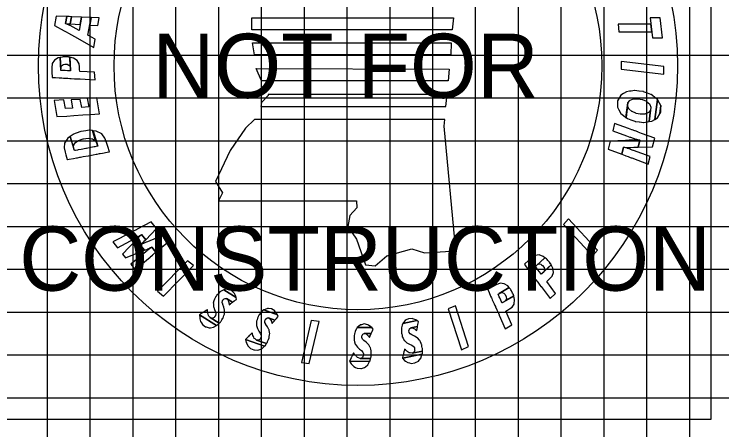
# Model space of a CAD drawing. Extents: x -20 to 684, y -10 to 430.
# Drawn here: x 626.44 to 659.5, y 370.5 to 389.91 of the extents above; entities that cross this region are included whole.
import ezdxf

# ---------------------------------------------------------------- set-up
doc = ezdxf.new("R2010")
doc.units = 0
for name, color, linetype in [('SHEET_CONSULTANT_STAMP', 7, 'Continuous'), ('SHEET_LOGO', 7, 'Continuous'), ('SHEET_LOGO_BG', 7, 'Continuous'), ('SHEET_PRELIM', 7, 'Continuous'), ('XS_SHEET_MAJOR_GRIDS', 7, 'Continuous'), ('XS_SHEET_MEDIUM_GRIDS', 7, 'Continuous'), ('XS_SHEET_MINOR_GRIDS', 7, 'Continuous')]:
    doc.layers.add(name, color=color, linetype=linetype)

msp = doc.modelspace()

# ---------------------------------------------------------------- linework, layer by layer
at = {"layer": 'SHEET_CONSULTANT_STAMP'}
msp.add_lwpolyline([(626, 371), (659, 371), (659, 404), (626, 404)], close=True, dxfattribs=at)
at = {"layer": 'SHEET_LOGO'}
for points in [[(629.812, 388.556), (630.158, 388.363), (630.23, 388.745), (629.884, 388.939), (630.037, 389.755), (629.59, 389.775), (629.473, 389.154), (629.052, 389.377), (629.044, 389.381), (628.943, 389.429), (628.941, 389.43), (628.834, 389.478), (628.895, 389.805), (628.409, 389.826), (628.327, 389.388), (628.771, 389.14), (628.875, 389.081), (628.878, 389.08), (628.977, 389.024), (628.985, 389.02), (629.404, 388.785)], [(628.95, 389.463), (629.058, 389.455), (629.122, 389.795), (629.013, 389.8), (629.01, 389.8), (628.896, 389.805), (628.834, 389.478), (628.947, 389.464)], [(629.066, 389.455), (629.525, 389.43), (629.59, 389.775), (629.13, 389.795), (629.122, 389.795), (629.058, 389.455)], [(629.97, 389.399), (630.35, 389.383), (630.417, 389.739), (630.037, 389.755)], [(637.546, 389.736), (646.972, 389.736), (646.903, 389.186), (637.546, 389.186)], [(656.188, 389.451), (654.654, 389.447), (654.693, 389.09), (656.227, 389.095)], [(656.622, 389.749), (656.156, 389.747), (656.258, 388.81), (656.725, 388.811)], [(637.58, 388.567), (646.851, 388.567), (646.834, 388.016), (637.666, 388.016)], [(629.524, 386.886), (630.22, 386.848), (630.201, 387.203), (629.505, 387.24), (629.5, 387.336), (629.494, 387.448), (629.474, 387.599), (629.388, 387.75), (629.209, 387.858), (629.049, 387.898), (629.081, 387.263), (629.081, 387.263), (629.07, 387.264), (629.024, 387.267), (629.017, 387.267), (628.935, 387.271), (628.823, 387.277), (628.764, 387.281), (628.723, 387.283), (628.656, 387.286), (628.632, 387.288), (628.628, 387.288), (628.597, 387.886), (628.502, 387.866), (628.327, 387.76), (628.223, 387.607), (628.199, 387.409), (628.209, 387.212), (628.222, 386.957), (628.223, 386.956), (628.257, 386.955), (628.369, 386.949), (628.55, 386.939), (628.646, 386.934), (628.65, 386.933), (628.674, 386.932), (628.742, 386.928), (628.782, 386.926), (628.841, 386.923), (628.954, 386.917), (629.035, 386.912), (629.042, 386.912), (629.088, 386.91), (629.099, 386.909), (629.1, 386.909), (629.259, 386.9), (629.433, 386.891), (629.511, 386.887), (629.523, 386.886)], [(629.011, 387.529), (629.06, 387.461), (629.037, 387.901), (628.991, 387.912), (628.983, 387.914), (628.902, 387.914), (628.79, 387.915), (628.731, 387.915), (628.691, 387.907), (628.624, 387.892), (628.601, 387.887), (628.597, 387.887), (628.624, 387.352), (628.625, 387.419), (628.645, 387.488), (628.709, 387.551), (628.749, 387.561), (628.807, 387.577), (628.92, 387.571), (629.003, 387.532)], [(629.075, 387.379), (629.08, 387.298), (629.049, 387.898), (629.048, 387.898), (629.037, 387.901), (629.06, 387.46)], [(656.791, 387.475), (654.804, 387.706), (654.8, 387.341), (656.788, 387.109)], [(646.765, 387.345), (646.714, 386.795), (637.993, 386.795), (637.752, 387.38)], [(638.303, 386.159), (638.303, 386.107), (637.993, 385.78), (637.959, 385.608), (646.61, 385.608), (646.662, 386.159)], [(654.676, 385.95), (654.627, 385.863), (654.625, 385.562), (654.688, 385.45), (654.787, 385.272), (654.909, 385.18), (655.022, 385.094), (655.111, 385.775), (655.112, 385.776), (655.196, 385.879), (655.206, 385.891), (655.211, 385.893), (655.37, 385.956), (655.374, 385.956), (655.382, 385.957), (655.575, 385.966), (655.582, 385.965), (655.593, 385.963), (655.776, 385.93), (655.786, 385.928), (655.795, 385.924), (655.974, 385.846), (655.981, 385.84), (655.983, 385.838), (656.12, 385.725), (656.121, 385.724), (656.132, 385.7), (656.187, 385.577), (656.169, 385.433), (656.099, 384.895), (656.226, 384.914), (656.371, 385), (656.492, 385.934), (656.37, 386.026), (656.257, 386.112), (656.256, 386.112), (656.191, 386.161), (656.178, 386.166), (656.177, 386.167), (656.033, 386.221), (656.03, 386.222), (656.023, 386.224), (655.842, 386.292), (655.834, 386.295), (655.824, 386.299), (655.639, 386.321), (655.628, 386.322), (655.621, 386.323), (655.433, 386.346), (655.425, 386.346), (655.42, 386.346), (655.267, 386.322), (655.261, 386.322), (655.253, 386.32), (655.181, 386.309), (655.18, 386.309), (655.053, 386.29), (654.908, 386.205), (654.776, 386.127)], [(629.99, 385.226), (630.434, 385.255), (630.303, 386.013), (629.859, 385.985), (629.929, 385.578), (629.596, 385.556), (629.531, 385.935), (629.098, 385.907), (629.163, 385.528), (628.837, 385.507), (628.767, 385.914), (628.306, 385.885), (628.437, 385.126), (628.898, 385.155), (629.224, 385.176), (629.657, 385.204)], [(656.589, 385.759), (656.492, 385.933), (656.371, 385), (656.501, 385.077), (656.604, 385.254), (656.654, 385.642)], [(655.093, 385.631), (655.111, 385.775), (655.022, 385.094), (655.023, 385.093)], [(655.148, 385.511), (655.093, 385.631), (655.023, 385.093), (655.088, 385.044), (655.096, 385.041), (655.1, 385.039), (655.244, 384.985), (655.249, 384.984), (655.249, 384.984), (655.256, 384.981), (655.439, 384.913), (655.445, 384.91), (655.456, 384.906), (655.641, 384.883), (655.651, 384.882), (655.66, 384.881), (655.846, 384.858), (655.854, 384.857), (655.856, 384.858), (656.011, 384.881), (656.012, 384.881), (656.026, 384.883), (656.099, 384.895), (656.099, 384.895), (656.169, 385.433), (656.168, 385.432), (656.084, 385.336), (656.068, 385.318), (656.067, 385.317), (655.907, 385.249), (655.904, 385.249), (655.897, 385.249), (655.706, 385.239), (655.697, 385.241), (655.687, 385.243), (655.504, 385.279), (655.493, 385.281), (655.487, 385.284), (655.306, 385.364), (655.299, 385.37), (655.295, 385.374), (655.158, 385.487), (655.155, 385.496)], [(656.653, 385.34), (656.654, 385.642), (656.604, 385.254), (656.653, 385.339)], [(637.666, 384.989), (637.254, 384.593), (636.531, 383.544), (635.843, 382.099), (636.17, 381.566), (635.981, 381.188), (642.431, 381.188), (642.448, 380.861), (642.121, 380.517), (642.035, 380.001), (642.431, 379.399), (642.861, 378.212), (643.308, 378.161), (643.858, 378.625), (645.011, 378.952), (645.613, 378.763), (647.075, 378.866), (646.524, 384.679), (646.559, 384.989)], [(655.134, 384.573), (654.49, 384.811), (654.402, 384.465), (655.048, 384.232), (655.048, 384.232), (655.206, 384.175), (655.227, 384.168), (655.354, 384.122), (655.36, 384.12), (655.488, 384.076), (655.508, 384.068), (655.67, 384.025), (655.589, 383.703), (656.267, 383.724), (656.367, 384.119), (655.751, 384.346), (655.593, 384.404), (655.573, 384.412), (655.446, 384.459), (655.439, 384.461), (655.312, 384.508), (655.292, 384.515)], [(630.887, 383.484), (630.888, 383.485), (630.814, 383.732), (630.76, 383.912), (630.683, 384.119), (630.532, 384.32), (630.271, 384.453), (630.134, 384.471), (630.35, 383.747), (630.349, 383.747), (630.32, 383.742), (630.216, 383.722), (630.177, 383.715), (630.024, 383.686), (629.815, 383.646), (629.793, 383.642), (629.567, 383.6), (629.433, 383.574), (629.405, 383.569), (629.302, 383.55), (629.261, 383.542), (629.256, 383.541), (629.06, 384.198), (628.942, 384.116), (628.791, 383.889), (628.773, 383.674), (628.818, 383.47), (628.856, 383.339), (628.921, 383.12), (628.922, 383.12), (628.937, 383.122), (629.014, 383.137), (629.221, 383.175), (629.357, 383.2), (629.362, 383.201), (629.403, 383.209), (629.506, 383.228), (629.534, 383.233), (629.668, 383.258), (629.895, 383.3), (629.917, 383.304), (630.126, 383.343), (630.279, 383.371), (630.318, 383.379), (630.422, 383.398), (630.451, 383.403), (630.452, 383.403), (630.576, 383.426), (630.786, 383.466), (630.872, 383.481)], [(630.106, 384.091), (630.242, 384.003), (630.102, 384.475), (629.987, 384.49), (629.944, 384.496), (629.79, 384.472), (629.579, 384.44), (629.558, 384.432), (629.343, 384.353), (629.215, 384.306), (629.191, 384.289), (629.101, 384.227), (629.101, 384.226), (629.065, 384.201), (629.06, 384.198), (629.237, 383.605), (629.213, 383.703), (629.224, 383.811), (629.3, 383.919), (629.325, 383.936), (629.444, 384.014), (629.66, 384.09), (629.683, 384.093), (629.894, 384.122), (630.063, 384.097)], [(630.242, 384.003), (630.311, 383.875), (630.134, 384.471), (630.102, 384.475)], [(630.311, 383.875), (630.35, 383.747), (630.134, 384.471), (630.134, 384.471)], [(654.993, 384.016), (654.282, 383.988), (654.186, 383.608), (654.83, 383.37), (654.912, 383.697), (655.083, 383.689), (655.105, 383.688), (655.245, 383.692), (655.252, 383.692), (655.392, 383.697), (655.415, 383.698), (655.589, 383.703), (655.67, 384.025), (655.499, 384.033), (655.477, 384.034), (655.337, 384.029), (655.33, 384.029), (655.19, 384.024), (655.168, 384.023)], [(655.074, 383.653), (654.912, 383.697), (654.83, 383.37), (654.988, 383.312), (655.009, 383.304), (655.136, 383.258), (655.142, 383.255), (655.269, 383.208), (655.289, 383.201), (656.063, 382.915), (656.15, 383.262), (655.376, 383.546), (655.356, 383.553), (655.229, 383.6), (655.222, 383.602), (655.095, 383.646)], [(631.869, 379.701), (631.047, 379.273), (631.265, 379.004), (632.081, 379.44), (632.119, 379.46), (632.131, 379.467), (632.131, 379.467), (632.136, 379.47), (632.136, 379.47), (632.212, 379.513), (632.226, 379.521), (632.25, 379.534), (632.256, 379.538), (632.258, 379.539), (632.26, 379.54), (632.344, 379.593), (632.353, 379.598), (632.391, 379.622), (632.587, 379.38), (633.097, 379.904), (632.848, 380.211), (632.191, 379.868), (632.15, 379.847), (632.141, 379.842), (632.052, 379.796), (632.05, 379.795), (632.047, 379.794), (632.042, 379.791), (632.017, 379.778), (632.003, 379.771), (631.924, 379.73), (631.92, 379.727), (631.907, 379.721)], [(652.096, 380.084), (653.458, 378.619), (653.698, 378.895), (652.336, 380.36)], [(632.139, 379.368), (631.51, 378.704), (631.647, 378.535), (632.531, 378.887), (632.333, 379.13), (632.364, 379.159), (632.374, 379.169), (632.378, 379.172), (632.441, 379.233), (632.452, 379.243), (632.471, 379.262), (632.476, 379.267), (632.477, 379.269), (632.479, 379.271), (632.549, 379.341), (632.556, 379.348), (632.587, 379.38), (632.391, 379.622), (632.359, 379.591), (632.351, 379.583), (632.281, 379.515), (632.279, 379.513), (632.277, 379.511), (632.273, 379.506), (632.254, 379.487), (632.243, 379.475), (632.182, 379.413), (632.178, 379.409), (632.169, 379.399)], [(632.372, 379.149), (632.333, 379.13), (632.531, 378.887), (632.572, 378.903), (632.571, 378.903), (632.585, 378.909), (632.59, 378.911), (632.675, 378.944), (632.69, 378.95), (632.69, 378.951), (632.716, 378.961), (632.716, 378.961), (632.723, 378.963), (632.725, 378.964), (632.728, 378.966), (632.727, 378.966), (632.818, 379.009), (632.828, 379.013), (632.87, 379.033), (633.062, 378.797), (633.618, 379.264), (633.37, 379.57), (632.667, 379.283), (632.623, 379.265), (632.613, 379.261), (632.52, 379.221), (632.517, 379.22), (632.515, 379.219), (632.509, 379.216), (632.483, 379.205), (632.468, 379.199), (632.389, 379.158), (632.384, 379.156)], [(632.589, 378.815), (631.888, 378.239), (632.095, 377.984), (632.79, 378.568), (632.822, 378.595), (632.833, 378.604), (632.837, 378.607), (632.837, 378.608), (632.903, 378.663), (632.915, 378.673), (632.936, 378.691), (632.941, 378.695), (632.943, 378.697), (632.945, 378.698), (633.02, 378.761), (633.028, 378.768), (633.062, 378.797), (632.87, 379.033), (632.834, 379.006), (632.826, 379), (632.747, 378.941), (632.745, 378.939), (632.743, 378.938), (632.738, 378.934), (632.717, 378.917), (632.705, 378.908), (632.637, 378.853), (632.633, 378.85), (632.622, 378.841)], [(651.057, 377.187), (651.473, 376.628), (651.734, 376.869), (651.317, 377.428), (651.387, 377.493), (651.47, 377.57), (651.573, 377.681), (651.634, 377.844), (651.603, 378.051), (651.531, 378.2), (651.064, 377.768), (651.064, 377.769), (651.057, 377.778), (651.03, 377.815), (651.025, 377.82), (650.977, 377.886), (650.909, 377.976), (650.874, 378.023), (650.85, 378.056), (650.809, 378.11), (650.795, 378.129), (650.793, 378.133), (651.233, 378.539), (651.157, 378.599), (650.963, 378.666), (650.779, 378.648), (650.611, 378.54), (650.466, 378.406), (650.278, 378.233), (650.279, 378.232), (650.299, 378.205), (650.366, 378.115), (650.475, 377.969), (650.532, 377.892), (650.534, 377.888), (650.549, 377.87), (650.589, 377.815), (650.613, 377.783), (650.649, 377.735), (650.716, 377.645), (650.765, 377.579), (650.769, 377.574), (650.796, 377.537), (650.803, 377.528), (650.803, 377.528), (650.898, 377.4), (651.003, 377.26), (651.049, 377.197), (651.056, 377.188)], [(651.222, 377.992), (651.202, 377.911), (651.525, 378.21), (651.505, 378.253), (651.501, 378.26), (651.449, 378.323), (651.378, 378.409), (651.341, 378.455), (651.309, 378.48), (651.255, 378.522), (651.236, 378.537), (651.233, 378.54), (650.84, 378.177), (650.892, 378.219), (650.957, 378.247), (651.047, 378.238), (651.081, 378.214), (651.13, 378.18), (651.197, 378.089), (651.22, 378)], [(634.536, 378.396), (633.134, 376.969), (633.42, 376.742), (634.822, 378.169)], [(651.149, 377.847), (651.089, 377.792), (651.531, 378.2), (651.53, 378.2), (651.525, 378.21), (651.202, 377.911)], [(649.098, 375.861), (649.384, 375.225), (649.691, 375.404), (649.405, 376.04), (649.487, 376.088), (649.584, 376.146), (649.71, 376.232), (649.804, 376.377), (649.819, 376.586), (649.78, 376.747), (649.231, 376.427), (649.231, 376.428), (649.226, 376.438), (649.208, 376.48), (649.204, 376.486), (649.171, 376.561), (649.125, 376.663), (649.101, 376.717), (649.084, 376.754), (649.056, 376.816), (649.047, 376.838), (649.045, 376.842), (649.562, 377.144), (649.501, 377.218), (649.326, 377.326), (649.143, 377.348), (648.956, 377.278), (648.785, 377.179), (648.564, 377.05), (648.564, 377.05), (648.578, 377.019), (648.625, 376.916), (648.699, 376.75), (648.738, 376.663), (648.74, 376.659), (648.75, 376.637), (648.778, 376.576), (648.794, 376.538), (648.818, 376.485), (648.864, 376.382), (648.898, 376.307), (648.901, 376.301), (648.92, 376.259), (648.924, 376.249), (648.924, 376.248), (648.99, 376.103), (649.061, 375.944), (649.093, 375.873), (649.098, 375.862)], [(635.695, 375.707), (635.594, 375.739), (636.014, 375.475), (636.034, 375.494), (636.045, 375.505), (636.076, 375.535), (636.09, 375.555), (636.108, 375.583), (636.148, 375.643), (636.194, 375.711), (636.2, 375.721), (636.22, 375.774), (636.244, 375.841), (636.269, 375.907), (636.269, 375.93), (636.272, 376.074), (636.268, 376.092), (636.232, 376.235), (636.185, 376.36), (636.184, 376.362), (636.162, 376.449), (636.172, 376.53), (636.177, 376.537), (636.215, 376.591), (636.214, 376.591), (636.217, 376.595), (636.225, 376.6), (636.291, 376.639), (636.32, 376.636), (636.319, 376.636), (636.369, 376.631), (636.642, 376.459), (636.723, 376.519), (636.824, 376.593), (636.807, 376.68), (636.235, 377.04), (636.172, 377.004), (636.057, 376.938), (635.989, 376.87), (635.973, 376.854), (635.964, 376.844), (635.915, 376.795), (635.909, 376.789), (635.905, 376.785), (635.871, 376.729), (635.866, 376.722), (635.828, 376.659), (635.796, 376.606), (635.795, 376.605), (635.773, 376.524), (635.745, 376.421), (635.746, 376.405), (635.758, 376.251), (635.768, 376.222), (635.803, 376.118), (635.84, 376.013), (635.856, 375.938), (635.859, 375.921), (635.843, 375.835), (635.8, 375.776), (635.781, 375.749), (635.755, 375.737), (635.711, 375.715)], [(636.3, 377.049), (636.235, 377.04), (636.807, 376.68), (636.797, 376.736), (636.733, 376.869), (636.724, 376.887), (636.593, 377.011), (636.593, 377.011), (636.463, 377.051), (636.422, 377.064)], [(649.434, 376.612), (649.396, 376.537), (649.777, 376.759), (649.766, 376.805), (649.764, 376.813), (649.727, 376.885), (649.676, 376.985), (649.65, 377.038), (649.624, 377.069), (649.58, 377.122), (649.565, 377.14), (649.563, 377.144), (649.101, 376.874), (649.161, 376.904), (649.231, 376.918), (649.316, 376.89), (649.344, 376.859), (649.384, 376.815), (649.43, 376.712), (649.434, 376.62)], [(636.473, 376.428), (636.485, 376.343), (636.542, 376.385), (636.546, 376.388), (636.553, 376.393), (636.612, 376.437), (636.623, 376.445), (636.623, 376.445), (636.642, 376.459), (636.368, 376.631), (636.432, 376.565), (636.438, 376.546), (636.471, 376.445), (636.472, 376.435)], [(649.331, 376.486), (649.261, 376.445), (649.78, 376.747), (649.78, 376.748), (649.777, 376.759), (649.396, 376.537)], [(646.723, 376.145), (647.34, 374.242), (647.673, 374.391), (647.057, 376.294)], [(635.135, 375.895), (635.106, 375.877), (635.901, 375.377), (635.932, 375.394), (636.014, 375.475), (635.594, 375.739), (635.543, 375.803), (635.515, 375.838), (635.501, 375.897), (635.493, 375.931), (635.482, 375.976), (635.477, 376.065), (635.474, 376.115), (635.436, 376.091), (635.369, 376.047), (635.339, 376.027), (635.316, 376.013), (635.277, 375.988), (635.264, 375.979), (635.238, 375.963)], [(635.238, 375.413), (635.381, 375.314), (635.408, 375.306), (635.553, 375.264), (635.608, 375.271), (635.748, 375.289), (635.784, 375.31), (635.901, 375.377), (635.106, 375.877), (635.108, 375.734), (635.12, 375.684), (635.148, 375.56), (635.19, 375.492)], [(637.862, 374.683), (637.757, 374.692), (638.224, 374.525), (638.239, 374.548), (638.248, 374.561), (638.272, 374.597), (638.28, 374.619), (638.292, 374.65), (638.319, 374.718), (638.348, 374.794), (638.353, 374.806), (638.36, 374.861), (638.37, 374.931), (638.379, 375.002), (638.375, 375.024), (638.347, 375.165), (638.338, 375.182), (638.273, 375.314), (638.2, 375.425), (638.198, 375.428), (638.159, 375.508), (638.15, 375.588), (638.154, 375.597), (638.179, 375.658), (638.178, 375.658), (638.18, 375.663), (638.187, 375.669), (638.243, 375.721), (638.271, 375.724), (638.271, 375.725), (638.32, 375.73), (638.625, 375.621), (638.691, 375.697), (638.773, 375.792), (638.738, 375.873), (638.101, 376.1), (638.048, 376.051), (637.95, 375.962), (637.898, 375.881), (637.886, 375.862), (637.879, 375.851), (637.842, 375.792), (637.838, 375.785), (637.835, 375.781), (637.813, 375.719), (637.81, 375.71), (637.786, 375.641), (637.767, 375.582), (637.766, 375.58), (637.762, 375.497), (637.757, 375.39), (637.762, 375.375), (637.807, 375.227), (637.822, 375.201), (637.879, 375.107), (637.938, 375.012), (637.97, 374.943), (637.977, 374.927), (637.979, 374.839), (637.95, 374.773), (637.937, 374.742), (637.914, 374.724), (637.876, 374.694)], [(638.163, 376.123), (638.102, 376.1), (638.738, 375.873), (638.716, 375.925), (638.625, 376.041), (638.612, 376.057), (638.457, 376.15), (638.457, 376.15), (638.322, 376.161), (638.279, 376.165)], [(638.466, 375.555), (638.497, 375.474), (638.543, 375.527), (638.546, 375.532), (638.552, 375.538), (638.6, 375.593), (638.609, 375.604), (638.609, 375.604), (638.625, 375.621), (638.32, 375.73), (638.397, 375.68), (638.406, 375.662), (638.46, 375.571), (638.464, 375.561)], [(640.32, 375.6), (639.861, 373.652), (640.224, 373.606), (640.683, 375.554)], [(645.121, 374.129), (645.027, 374.082), (645.512, 374.181), (645.513, 374.209), (645.514, 374.225), (645.516, 374.268), (645.511, 374.292), (645.506, 374.324), (645.493, 374.396), (645.479, 374.476), (645.477, 374.488), (645.454, 374.54), (645.426, 374.605), (645.398, 374.67), (645.382, 374.687), (645.285, 374.793), (645.269, 374.803), (645.145, 374.882), (645.025, 374.939), (645.022, 374.94), (644.947, 374.988), (644.898, 375.053), (644.896, 375.062), (644.886, 375.127), (644.886, 375.127), (644.885, 375.132), (644.888, 375.14), (644.908, 375.214), (644.931, 375.232), (644.931, 375.232), (644.97, 375.262), (645.286, 375.327), (645.304, 375.426), (645.325, 375.55), (645.254, 375.601), (644.591, 375.466), (644.57, 375.396), (644.533, 375.269), (644.531, 375.173), (644.53, 375.15), (644.53, 375.137), (644.529, 375.067), (644.529, 375.059), (644.528, 375.054), (644.542, 374.99), (644.544, 374.981), (644.56, 374.909), (644.573, 374.849), (644.574, 374.847), (644.613, 374.774), (644.664, 374.679), (644.676, 374.669), (644.791, 374.566), (644.818, 374.552), (644.915, 374.501), (645.015, 374.45), (645.078, 374.407), (645.092, 374.397), (645.14, 374.324), (645.149, 374.251), (645.154, 374.219), (645.144, 374.192), (645.127, 374.146)], [(644.632, 375.517), (644.591, 375.466), (645.254, 375.601), (645.207, 375.634), (645.069, 375.686), (645.05, 375.693), (644.869, 375.692), (644.869, 375.692), (644.748, 375.632), (644.71, 375.613)], [(642.7, 373.864), (642.598, 373.839), (643.094, 373.83), (643.101, 373.857), (643.105, 373.872), (643.116, 373.914), (643.117, 373.938), (643.118, 373.971), (643.121, 374.044), (643.125, 374.126), (643.126, 374.138), (643.115, 374.193), (643.101, 374.262), (643.088, 374.332), (643.076, 374.352), (643.004, 374.476), (642.991, 374.49), (642.886, 374.594), (642.782, 374.676), (642.78, 374.677), (642.716, 374.74), (642.683, 374.814), (642.683, 374.823), (642.687, 374.889), (642.687, 374.889), (642.687, 374.894), (642.691, 374.902), (642.727, 374.969), (642.754, 374.982), (642.753, 374.982), (642.798, 375.003), (643.121, 374.998), (643.16, 375.091), (643.207, 375.207), (643.148, 375.272), (642.472, 375.283), (642.437, 375.22), (642.373, 375.104), (642.35, 375.01), (642.345, 374.989), (642.341, 374.976), (642.325, 374.908), (642.323, 374.9), (642.322, 374.895), (642.322, 374.829), (642.322, 374.82), (642.321, 374.747), (642.321, 374.685), (642.321, 374.683), (642.344, 374.603), (642.374, 374.5), (642.383, 374.487), (642.473, 374.362), (642.496, 374.342), (642.58, 374.271), (642.667, 374.2), (642.719, 374.145), (642.73, 374.132), (642.761, 374.05), (642.755, 373.977), (642.752, 373.944), (642.736, 373.92), (642.71, 373.879)], [(642.523, 375.325), (642.472, 375.283), (643.148, 375.272), (643.11, 375.315), (642.987, 375.395), (642.97, 375.406), (642.793, 375.444), (642.793, 375.444), (642.661, 375.411), (642.62, 375.401)], [(645.185, 375.188), (645.253, 375.135), (645.265, 375.204), (645.266, 375.21), (645.267, 375.218), (645.28, 375.29), (645.283, 375.304), (645.282, 375.304), (645.286, 375.327), (644.97, 375.262), (645.061, 375.259), (645.079, 375.249), (645.172, 375.198), (645.18, 375.192)], [(637.275, 374.745), (637.25, 374.721), (638.135, 374.404), (638.161, 374.428), (638.224, 374.525), (637.757, 374.692), (637.693, 374.743), (637.658, 374.772), (637.632, 374.825), (637.617, 374.857), (637.596, 374.899), (637.572, 374.985), (637.559, 375.033), (637.527, 375.001), (637.471, 374.944), (637.445, 374.918), (637.426, 374.899), (637.394, 374.866), (637.382, 374.854), (637.361, 374.833)], [(642.992, 374.884), (643.047, 374.817), (643.074, 374.882), (643.076, 374.888), (643.079, 374.895), (643.107, 374.963), (643.112, 374.976), (643.112, 374.976), (643.121, 374.998), (642.798, 375.003), (642.886, 374.98), (642.901, 374.966), (642.982, 374.897), (642.988, 374.889)], [(637.479, 374.297), (637.641, 374.231), (637.669, 374.229), (637.82, 374.219), (637.872, 374.238), (638.004, 374.286), (638.035, 374.314), (638.135, 374.404), (637.251, 374.72), (637.284, 374.582), (637.306, 374.536), (637.361, 374.421), (637.416, 374.363)], [(644.586, 373.878), (644.578, 373.844), (645.498, 374.032), (645.509, 374.066), (645.512, 374.181), (645.027, 374.082), (644.945, 374.093), (644.9, 374.099), (644.85, 374.132), (644.82, 374.151), (644.781, 374.176), (644.716, 374.237), (644.68, 374.271), (644.669, 374.228), (644.651, 374.15), (644.642, 374.114), (644.636, 374.088), (644.625, 374.043), (644.622, 374.027), (644.614, 373.998)], [(642.124, 373.734), (642.109, 373.703), (643.048, 373.688), (643.066, 373.719), (643.094, 373.83), (642.598, 373.839), (642.521, 373.867), (642.479, 373.883), (642.437, 373.925), (642.412, 373.95), (642.379, 373.983), (642.329, 374.057), (642.3, 374.098), (642.281, 374.058), (642.246, 373.986), (642.23, 373.953), (642.218, 373.929), (642.198, 373.887), (642.191, 373.872), (642.178, 373.846)], [(644.993, 373.601), (645.166, 373.628), (645.191, 373.641), (645.325, 373.71), (645.359, 373.753), (645.448, 373.863), (645.46, 373.903), (645.498, 374.032), (644.578, 373.844), (644.678, 373.743), (644.721, 373.715), (644.828, 373.645), (644.904, 373.624)], [(642.462, 373.375), (642.636, 373.365), (642.663, 373.372), (642.809, 373.411), (642.852, 373.445), (642.962, 373.534), (642.982, 373.57), (643.048, 373.688), (642.109, 373.703), (642.185, 373.583), (642.22, 373.546), (642.31, 373.455), (642.38, 373.418)]]:
    msp.add_lwpolyline(points, close=True, dxfattribs=at)
for radius in [14.927, 11.393]:
    msp.add_circle((642.5, 387.5), radius, dxfattribs=at)
at = {"layer": 'SHEET_LOGO_BG'}
msp.add_lwpolyline([(626, 371), (659, 371), (659, 404), (626, 404)], close=True, dxfattribs=at)
at = {"layer": 'SHEET_PRELIM'}
msp.add_lwpolyline([(626, 371), (659, 371), (659, 404), (626, 404)], close=True, dxfattribs=at)
at = {"layer": 'XS_SHEET_MAJOR_GRIDS'}
for p, q in [((640, 0), (640, 404)), ((10, 380), (680, 380))]:
    msp.add_line(p, q, dxfattribs=at)
at = {"layer": 'XS_SHEET_MEDIUM_GRIDS'}
for p, q in [((630, 0), (630, 404)), ((650, 0), (650, 404))]:
    msp.add_line(p, q, dxfattribs=at)
at = {"layer": 'XS_SHEET_MINOR_GRIDS'}
for p, q in [((628, 0), (628, 404)), ((632, 0), (632, 404)), ((634, 0), (634, 404)), ((636, 0), (636, 404)), ((638, 0), (638, 404)), ((642, 0), (642, 404)), ((644, 0), (644, 404)), ((646, 0), (646, 404)), ((648, 0), (648, 404)), ((652, 0), (652, 404)), ((654, 0), (654, 404)), ((656, 0), (656, 404)), ((658, 0), (658, 404)), ((10, 388), (680, 388)), ((10, 386), (680, 386)), ((10, 384), (680, 384)), ((10, 382), (680, 382)), ((10, 378), (680, 378)), ((10, 376), (680, 376)), ((10, 374), (680, 374)), ((10, 372), (680, 372))]:
    msp.add_line(p, q, dxfattribs=at)

# ---------------------------------------------------------------- texts
at = {"layer": 'SHEET_PRELIM'}
for s, p in [('NOT FOR', (632.9, 386)), ('CONSTRUCTION', (626.68, 377))]:
    msp.add_text(s, height=3, dxfattribs=at).set_placement(p)

doc.saveas('drawing.dxf')
